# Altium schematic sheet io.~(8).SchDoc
size Letter
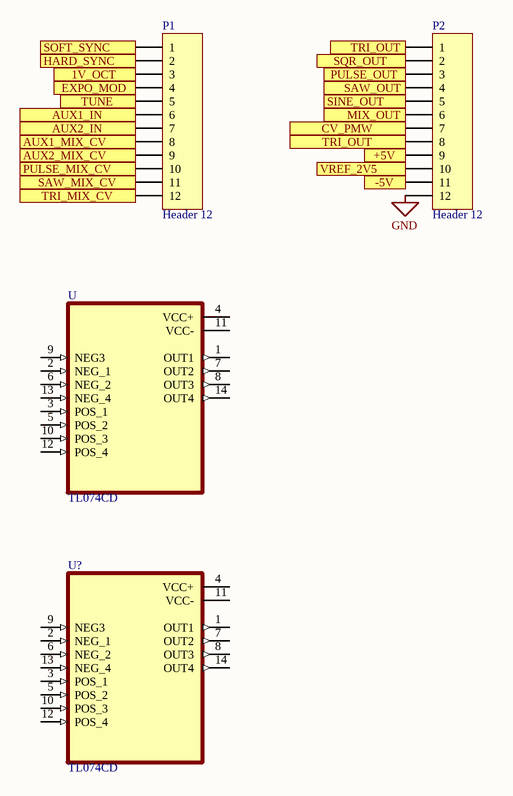
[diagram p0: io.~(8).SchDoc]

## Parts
P1  Header 12  [HDR1X12]
P2  Header 12  [HDR1X12]
U  TL074CD  [SOIC127P600X175-14N]
U?  TL074CD  [SOIC127P600X175-14N]

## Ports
1V_OCT, +5V, -5V, AUX1_IN, AUX1_MIX_CV, AUX2_IN, AUX2_MIX_CV, CV_PMW, EXPO_MOD, HARD_SYNC, MIX_OUT, PULSE_MIX_CV, PULSE_OUT, SAW_MIX_CV, SAW_OUT, SINE_OUT, SOFT_SYNC, SQR_OUT, TRI_MIX_CV, TRI_OUT, TUNE, VREF_2V5

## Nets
GND: P2.12
1V_OCT: P1.3 ; port 1V_OCT
+5V: P2.9 ; port +5V
-5V: P2.11 ; port -5V
AUX1_IN: P1.6 ; port AUX1_IN
AUX1_MIX_CV: P1.8 ; port AUX1_MIX_CV
AUX2_IN: P1.7 ; port AUX2_IN
AUX2_MIX_CV: P1.9 ; port AUX2_MIX_CV
CV_PMW: P2.7 ; port CV_PMW
EXPO_MOD: P1.4 ; port EXPO_MOD
HARD_SYNC: P1.2 ; port HARD_SYNC
MIX_OUT: P2.6 ; port MIX_OUT
PULSE_MIX_CV: P1.10 ; port PULSE_MIX_CV
PULSE_OUT: P2.3 ; port PULSE_OUT
SAW_MIX_CV: P1.11 ; port SAW_MIX_CV
SAW_OUT: P2.4 ; port SAW_OUT
SINE_OUT: P2.5 ; port SINE_OUT
SOFT_SYNC: P1.1 ; port SOFT_SYNC
SQR_OUT: P2.2 ; port SQR_OUT
TRI_MIX_CV: P1.12 ; port TRI_MIX_CV
TRI_OUT: P2.1 P2.8 ; port TRI_OUT
TUNE: P1.5 ; port TUNE
VREF_2V5: P2.10 ; port VREF_2V5

Not connected (* = marked no-connect by the designer): U 1(OUT1) 2(NEG_1) 3(POS_1) 4(VCC+) 5(POS_2) 6(NEG_2) 7(OUT2) 8(OUT3) 9(NEG3) 10(POS_3) 11(VCC-) 12(POS_4) 13(NEG_4) 14(OUT4); U? 1(OUT1) 2(NEG_1) 3(POS_1) 4(VCC+) 5(POS_2) 6(NEG_2) 7(OUT2) 8(OUT3) 9(NEG3) 10(POS_3) 11(VCC-) 12(POS_4) 13(NEG_4) 14(OUT4)

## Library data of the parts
P1 P2 = Header 12: Header, 12-Pin
U U? = TL074CD: Quad Low-Noise JFET-Input General-Purpose Operational Amplifier 14-SOIC 0 to 70; MF: Texas Instruments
